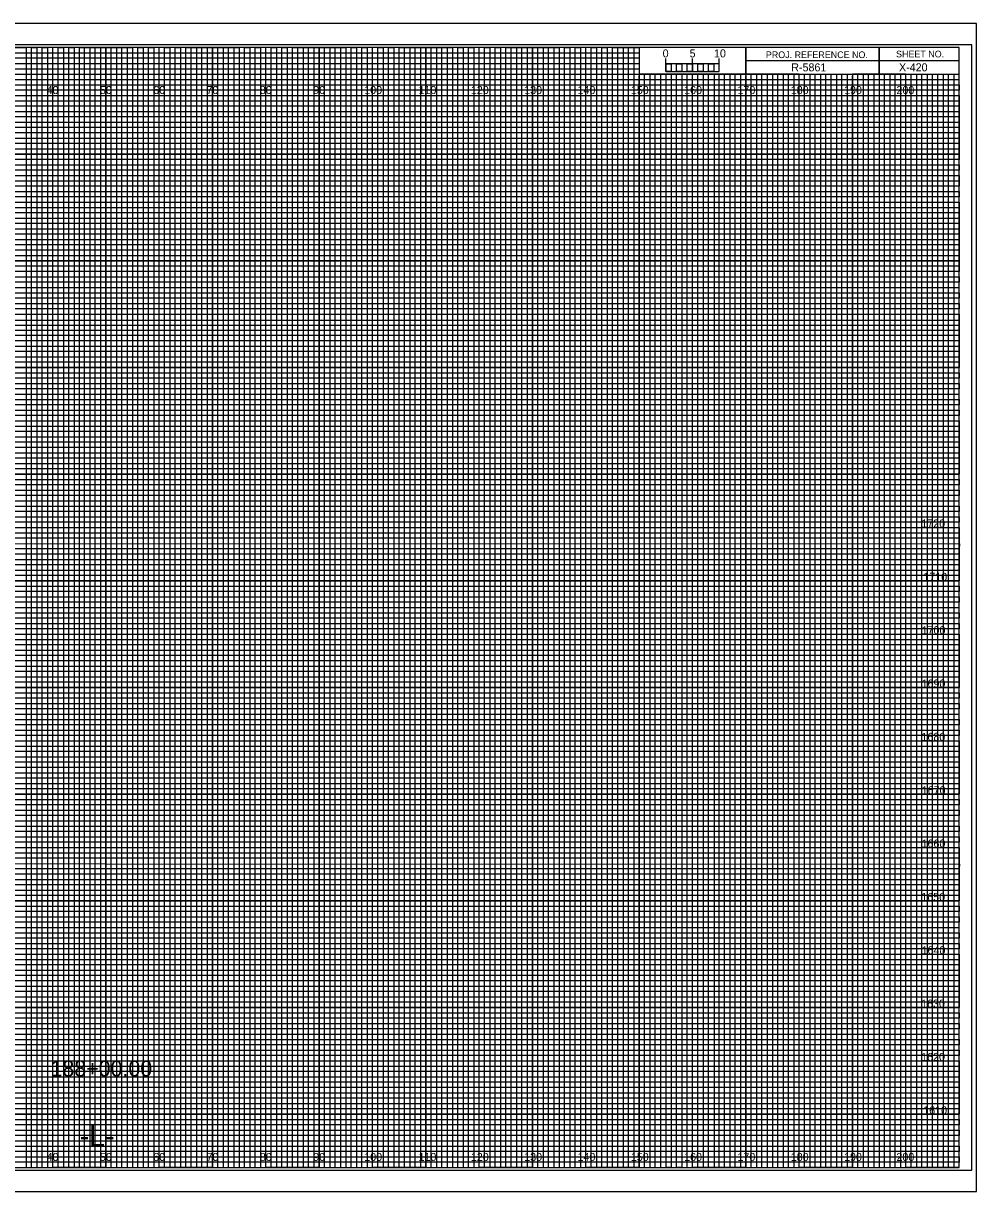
# Model space of a CAD drawing. Extents: x -13 to 323, y -5 to 6154.
# Drawn here: x 144.5 to 323.3, y 3515.5 to 3734.5 of the extents above; entities that cross this region are included whole.
import ezdxf

# ---------------------------------------------------------------- set-up
doc = ezdxf.new("R2010")
doc.units = 0
for name, color, linetype in [('Exist CMT Ground Line', 7, 'Continuous'), ('Prop Horizontal Alignment', 7, 'Continuous'), ('Prop Retaining Wall', 7, 'Continuous'), ('Prop XS Alignment Label', 7, 'Continuous'), ('Prop XS Bar Scale Labels', 7, 'Continuous'), ('Prop XS DDE', 7, 'Continuous'), ('Prop XS DDE Elevations', 7, 'Continuous'), ('Prop XS DDE Slope Text', 7, 'Continuous'), ('Prop XS Earthwork Shape', 7, 'Continuous'), ('Prop XS Elevation Labels', 7, 'Continuous'), ('Prop XS Project Number', 7, 'Continuous'), ('Prop XS Sheet Number', 7, 'Continuous'), ('Prop XS Station Labels', 7, 'Continuous'), ('Raster_Level_0', 7, 'Continuous'), ('Scratch_Level_3', 7, 'Continuous'), ('Sheet Cutting Line CELL', 7, 'Continuous')]:
    doc.layers.add(name, color=color, linetype=linetype)

msp = doc.modelspace()

# ---------------------------------------------------------------- linework, layer by layer
at = {"layer": 'Exist CMT Ground Line'}
for p, q in [((265, 3725.49), (265, 3727.9)), ((265, 3726.9), (265, 3727.9)), ((270, 3725.49), (270, 3727.9)), ((275, 3725.49), (275, 3727.9)), ((275, 3726.9), (275, 3727.9))]:
    msp.add_line(p, q, dxfattribs=at)
for points in [[(275, 3726.9), (265, 3726.9), (265, 3725.49), (275, 3725.49)], [(265, 3726.9), (266, 3726.9), (266, 3725.49), (265, 3725.49)], [(267, 3726.9), (268, 3726.9), (268, 3725.49), (267, 3725.49)], [(269, 3726.9), (270, 3726.9), (270, 3725.49), (269, 3725.49)], [(271, 3726.9), (272, 3726.9), (272, 3725.49), (271, 3725.49)], [(273, 3726.9), (274, 3726.9), (274, 3725.49), (273, 3725.49)]]:
    msp.add_lwpolyline(points, close=True, dxfattribs=at)
at = {"layer": 'Prop Retaining Wall'}
for p, q in [((0, 3729), (260, 3729)), ((260, 3727.98), (0, 3727.98)), ((260, 3729), (260, 3727.98)), ((0, 3727), (260, 3727)), ((260, 3725.89), (0, 3725.89)), ((260, 3727), (260, 3725.89)), ((0, 3724), (320, 3724))]:
    msp.add_line(p, q, dxfattribs=at)
for points in [[(0, 3723), (270, 3723), (320, 3723), (320, 3722), (0, 3722)], [(0, 3721), (320, 3721), (320, 3719), (0, 3719)], [(0, 3718), (320, 3718), (320, 3717), (0, 3716.98)], [(0, 3716), (320, 3716), (320, 3714), (0, 3714)], [(0, 3713), (320, 3713), (320, 3712), (0, 3712)], [(0, 3711), (320, 3711), (320, 3709), (0, 3709)], [(0, 3708), (320, 3708), (320, 3707), (0, 3707)], [(0, 3706), (320, 3706), (320, 3704), (0, 3704)], [(0, 3703), (320, 3703), (320, 3702), (0, 3702)], [(0, 3701), (320, 3701), (320, 3699), (0, 3699)], [(0, 3698), (320, 3698), (320, 3697), (0, 3697)], [(0, 3696), (320, 3696), (320, 3693.95), (320, 3693), (320, 3692), (0, 3692)], [(0, 3694), (320, 3694), (320, 3693), (0, 3693)], [(0, 3691), (320, 3691), (320, 3689), (0, 3689.03)], [(0, 3689.03), (320, 3689), (320, 3688), (0, 3688)], [(0, 3687), (320, 3687), (320, 3686), (0, 3686)], [(0, 3684), (320, 3684), (320, 3683), (0, 3683)], [(0, 3682), (320, 3682), (320, 3681), (0, 3681)], [(-0.07, 3678.89), (320, 3678.89), (320, 3677.88), (-0.07, 3677.88)], [(0, 3677), (320, 3677), (320, 3676), (0, 3676)], [(0, 3674), (320, 3674), (320, 3673), (0, 3673)], [(0, 3672), (320, 3672), (320, 3671), (0, 3671)], [(0, 3669), (320, 3669), (320, 3668), (0, 3668)], [(0, 3667), (320, 3667), (320, 3666), (0, 3666)], [(0, 3664), (320, 3664), (320, 3663), (0, 3663)], [(0, 3662), (320, 3662), (320, 3661), (0, 3661)], [(0, 3659), (320, 3659), (319.99, 3657.98), (0, 3658)], [(0, 3657), (320, 3657), (320, 3656), (0, 3656)], [(0, 3654), (320, 3654), (320, 3653), (0, 3653)], [(0, 3652), (320, 3652), (320, 3651), (0, 3651)], [(0, 3649), (320, 3649), (320, 3648), (0, 3648)], [(0, 3647), (320, 3647), (320, 3646), (0, 3646)], [(0, 3644), (320, 3644), (320, 3643), (0, 3643)], [(0, 3642), (320, 3642), (320, 3641), (0, 3641)], [(0, 3639), (320, 3639), (320, 3638), (0, 3638)], [(0, 3636.99), (320.07, 3636.91), (320, 3636), (0, 3636)], [(0, 3634), (320, 3634), (320, 3633), (0, 3633)], [(0, 3632), (320, 3632), (320, 3631), (0, 3631)], [(0, 3629), (320, 3629), (320, 3628), (0, 3628)], [(0, 3627), (320, 3627), (320, 3626), (0, 3626)], [(0, 3624), (320, 3624), (320, 3623), (0, 3623)], [(0, 3622), (320, 3622), (320, 3621), (0, 3621)], [(0, 3619), (320, 3619), (320, 3618), (0, 3618)], [(0, 3617), (320, 3617), (320, 3616), (0, 3616)], [(0, 3614), (320, 3614), (320, 3613), (0, 3613)], [(0, 3612), (320, 3612), (320, 3611), (0, 3611)], [(0, 3609), (320, 3609), (320, 3608), (0, 3608)], [(0, 3607), (320, 3607), (320, 3606), (0, 3606)], [(0, 3604), (320, 3604), (320, 3603), (0, 3603)], [(0, 3602), (320, 3602), (320, 3601), (0, 3601)], [(0, 3599), (320, 3599), (319.99, 3597.98), (0, 3598)], [(0, 3597), (320, 3597), (320, 3596), (0, 3596)], [(0, 3594), (320, 3594), (320, 3593), (0, 3593)], [(0, 3592), (320, 3592), (320, 3591), (0, 3591)], [(0, 3589), (320, 3589), (320, 3588), (0, 3588)], [(0, 3587), (320, 3587), (320, 3586), (0, 3586)], [(0, 3584), (320, 3584), (320, 3583), (0, 3583)], [(0, 3582), (320, 3582), (320, 3581), (0, 3581)], [(0, 3579), (320, 3579), (320, 3578), (0, 3578)], [(0, 3576.99), (320.07, 3576.91), (320, 3576), (0, 3576)], [(0, 3574), (320, 3574), (320, 3573), (0, 3573)], [(0, 3572), (320, 3572), (320, 3571), (0, 3571)], [(0, 3569), (320, 3569), (320, 3568), (0, 3568)], [(0, 3567), (320, 3567), (320, 3566), (0, 3566)], [(0, 3564), (320, 3564), (320, 3563), (0, 3563)], [(0, 3562), (320, 3562), (320, 3561), (0, 3561)], [(0, 3559), (320, 3559), (320, 3558), (0, 3558)], [(0, 3557), (320, 3557), (320, 3556), (0, 3556)], [(0, 3554), (320, 3554), (320, 3553), (0, 3553)], [(0, 3552), (320, 3552), (320, 3551), (0, 3551)], [(0, 3549), (320, 3549), (320, 3548), (0, 3548)], [(0, 3547), (320, 3547), (320, 3546), (0, 3546)], [(0, 3544), (320, 3544), (320, 3543), (0, 3543)], [(0, 3542), (320, 3542), (320, 3541), (0, 3541)], [(0, 3539), (320, 3539), (320, 3538), (0, 3538)], [(0, 3537), (320, 3537), (320, 3536), (0, 3536)], [(0, 3534), (320, 3534), (320, 3533), (0, 3533)], [(0, 3532), (320, 3532), (320, 3531), (0, 3531)], [(0, 3529), (320, 3529), (320, 3528), (0, 3528)], [(0, 3527), (320, 3527), (320, 3526), (0, 3526)], [(0, 3524), (320, 3524), (320, 3523), (0, 3523)], [(0, 3522), (320, 3522), (320, 3521), (0, 3521)]]:
    msp.add_lwpolyline(points, dxfattribs=at)
at = {"layer": 'Prop XS Alignment Label'}
for p, q in [((305, 3730), (305, 3725)), ((305, 3725), (305, 3730)), ((280, 3727.5), (280, 3725)), ((320, 3727.49), (280, 3727.49)), ((280, 3725), (320, 3725))]:
    msp.add_line(p, q, dxfattribs=at)
for points in [[(320, 3730), (0, 3730), (0, 3520), (320, 3520)], [(280, 3730), (260, 3730), (260, 3725.03), (280, 3725.03)], [(320, 3730), (280, 3730), (280, 3725), (320, 3725)]]:
    msp.add_lwpolyline(points, close=True, dxfattribs=at)
at = {"layer": 'Prop XS DDE'}
msp.add_lwpolyline([(-13.4, 3515.5), (323.3, 3515.5), (323.3, 3734.5), (-13.4, 3734.5)], close=True, dxfattribs=at)
at = {"layer": 'Prop XS DDE Elevations'}
for p, q in [((150, 3520), (150, 3730)), ((160, 3520), (160, 3730)), ((170, 3520), (170, 3730)), ((180, 3520), (180, 3730)), ((190, 3520), (190, 3730)), ((200, 3520), (200, 3730)), ((210, 3520), (210, 3730)), ((220, 3520), (220, 3730)), ((230, 3520), (230, 3730)), ((240, 3520), (240, 3730)), ((250, 3520), (250, 3730)), ((260, 3520), (260, 3724.69)), ((270, 3520), (270, 3724.69)), ((280, 3520), (280, 3724.69)), ((290, 3520), (290, 3724.69)), ((300, 3520), (300, 3724.69)), ((310, 3520), (310, 3724.69)), ((0, 3720), (320, 3720)), ((0, 3710), (320, 3710)), ((0, 3700), (320, 3700)), ((0, 3690), (320, 3690)), ((0, 3680), (320, 3680)), ((0, 3670), (320, 3670)), ((0, 3660), (320, 3660)), ((0, 3650), (320, 3650)), ((0, 3640), (320, 3640)), ((0, 3630), (320, 3630)), ((0, 3620), (320, 3620)), ((0, 3610), (320, 3610)), ((0, 3600), (320, 3600)), ((0, 3590), (320, 3590)), ((0, 3580), (320, 3580)), ((0, 3570), (320, 3570)), ((0, 3560), (320, 3560)), ((0, 3550), (320, 3550)), ((0, 3540), (320, 3540)), ((0, 3530), (320, 3530))]:
    msp.add_line(p, q, dxfattribs=at)
at = {"layer": 'Prop XS DDE Slope Text'}
msp.add_lwpolyline([(-10.8, 3519.5), (322.4, 3519.5), (322.4, 3730.5), (-10.8, 3730.5)], close=True, dxfattribs=at)
at = {"layer": 'Prop XS Earthwork Shape'}
for p, q in [((150, 3730), (140, 3730)), ((150, 3520), (150, 3730)), ((170, 3730), (160, 3730)), ((160, 3730), (160, 3520)), ((170, 3520), (170, 3730)), ((190, 3730), (180, 3730)), ((180, 3730), (180, 3520)), ((190, 3520), (190, 3730)), ((210, 3730), (200, 3730)), ((200, 3730), (200, 3520)), ((210, 3520), (210, 3730)), ((230, 3730), (220, 3730)), ((220, 3730), (220, 3520)), ((230, 3520), (230, 3730)), ((250, 3730), (240, 3730)), ((240, 3730), (240, 3520)), ((250, 3520), (250, 3730)), ((260, 3730), (260, 3520)), ((270, 3520), (270, 3725)), ((290, 3725), (280, 3725)), ((280, 3725), (280, 3520)), ((290, 3520), (290, 3725)), ((310, 3725), (300, 3725)), ((300, 3725), (300, 3520)), ((310, 3520), (310, 3725)), ((160, 3520), (150, 3520)), ((180, 3520), (170, 3520)), ((200, 3520), (190, 3520)), ((220, 3520), (210, 3520)), ((240, 3520), (230, 3520)), ((260, 3520), (250, 3520)), ((280, 3520), (270, 3520)), ((300, 3520), (290, 3520)), ((320, 3520), (310, 3520)), ((320, 3520), (320, 3520))]:
    msp.add_line(p, q, dxfattribs=at)
for points in [[(0, 3720), (320, 3720), (320, 3710), (0, 3710)], [(0, 3700), (320, 3700), (320, 3690), (0, 3690)], [(0, 3680), (320, 3680), (320, 3670), (0, 3670)], [(0, 3660), (320, 3660), (320, 3650), (0, 3650)], [(0, 3640), (320, 3640), (320, 3630), (0, 3630)], [(0, 3620), (320, 3620), (320, 3610), (0, 3610)], [(0, 3600), (320, 3600), (320, 3590), (0, 3590)], [(0, 3580), (320, 3580), (320, 3570), (0, 3570)], [(0, 3560), (320, 3560), (320, 3550), (0, 3550)], [(0, 3540), (320, 3540), (320, 3530), (0, 3530)]]:
    msp.add_lwpolyline(points, dxfattribs=at)
at = {"layer": 'Prop XS Elevation Labels'}
for p, q in [((267, 3725), (266.01, 3725)), ((266.01, 3725), (266.01, 3520)), ((267, 3520), (267, 3725)), ((269, 3725), (268, 3725)), ((268, 3725), (268, 3520)), ((269, 3520), (269, 3725)), ((266.01, 3520), (265, 3520)), ((268, 3520), (267, 3520))]:
    msp.add_line(p, q, dxfattribs=at)
for points in [[(145, 3520), (146, 3520), (146, 3730), (147, 3730), (147, 3520)], [(147, 3520), (148, 3520), (148, 3730), (149, 3730), (149, 3520)], [(150, 3520), (151, 3520), (151, 3730), (152, 3730), (152, 3520)], [(152, 3520), (153, 3520), (153, 3730), (154, 3730), (154, 3520)], [(155, 3520), (156, 3520), (156, 3730), (157, 3730), (157, 3520)], [(157, 3520), (158, 3520), (158, 3730), (159, 3730), (159, 3520)], [(160, 3520), (161, 3520), (161, 3730), (162, 3730), (162, 3520)], [(162, 3520), (163, 3520), (163, 3730), (164, 3730), (164, 3520)], [(165, 3520), (166, 3520), (166, 3730), (167, 3730), (167, 3520)], [(167, 3520), (168, 3520), (168, 3730), (169, 3730), (169, 3520)], [(170, 3520), (171, 3520), (171, 3730), (172, 3730), (172, 3520)], [(172, 3520), (173, 3520), (173, 3730), (174, 3730), (174, 3520)], [(175, 3520), (176, 3520), (176, 3730), (177, 3730), (177, 3520)], [(177, 3520), (178, 3520), (178, 3730), (179, 3730), (179, 3520)], [(180, 3520), (181, 3520), (181, 3730), (182, 3730), (182, 3520)], [(182, 3520), (183, 3520), (183, 3730), (184, 3730), (184, 3520)], [(185, 3520), (186, 3520), (186, 3730), (187, 3730), (187, 3520)], [(187, 3520), (188, 3520), (188, 3730), (189, 3730), (189, 3520)], [(190, 3520), (191, 3520), (191, 3730), (192, 3730), (192, 3520)], [(192, 3520), (193, 3520), (193, 3730), (194, 3730), (194, 3520)], [(195, 3520), (196, 3520), (196, 3730), (197, 3730), (197, 3520)], [(197, 3520), (198, 3520), (198, 3730), (199, 3730), (199, 3520)], [(200, 3520), (201, 3520), (201, 3730), (202, 3730), (202, 3520)], [(202, 3520), (203, 3520), (203, 3730), (204, 3730), (204, 3520)], [(205, 3520), (206, 3520), (206, 3730), (207, 3730), (207, 3520)], [(207, 3520), (208, 3520), (208, 3730), (209, 3730), (209, 3520)], [(210, 3520), (211, 3520), (211, 3730), (212, 3730), (212, 3520)], [(212, 3520), (213, 3520), (213, 3730), (214, 3730), (214, 3520)], [(215, 3520), (216, 3520), (216, 3730), (217, 3730), (217, 3520)], [(217, 3520), (218, 3520), (218, 3730), (219, 3730), (219, 3520)], [(220, 3520), (221, 3520), (221, 3730), (222, 3730), (222, 3520)], [(222, 3520), (223, 3520), (223, 3730), (224, 3730), (224, 3520)], [(225, 3520), (226, 3520), (226, 3730), (227, 3730), (227, 3520)], [(227, 3520), (228, 3520), (228, 3730), (229, 3730), (229, 3520)], [(230, 3520), (231, 3520), (231, 3730), (232, 3730), (232, 3520)], [(232, 3520), (233, 3520), (233, 3730), (234, 3730), (234, 3520)], [(235, 3520), (236, 3520), (236, 3730), (237, 3730), (237, 3520)], [(237, 3520), (238, 3520), (238, 3730), (239, 3730), (239, 3520)], [(240, 3520), (241, 3520), (241, 3730), (242, 3730), (242, 3520)], [(242, 3520), (243, 3520), (243, 3730), (244, 3730), (244, 3520)], [(245, 3520), (246, 3520), (246, 3730), (247, 3730), (247, 3520)], [(247, 3520), (248, 3520), (248, 3730), (249, 3730), (249, 3520)], [(250, 3520), (251, 3520), (251, 3730), (252, 3730), (252, 3520)], [(252, 3520), (253, 3520), (253, 3730), (254, 3730), (254, 3520)], [(255, 3520), (256, 3520), (256, 3730), (257, 3730), (257, 3520)], [(257, 3520), (258, 3520), (258, 3730), (259, 3730), (259, 3520)], [(260, 3520), (261, 3520), (261, 3725), (262.02, 3725), (262.02, 3520)], [(262, 3520), (263, 3520), (263, 3725), (263.99, 3725), (263.99, 3520)], [(270, 3520), (270.98, 3520), (270.98, 3725), (272, 3725), (272, 3520)], [(272, 3520), (273, 3520), (273, 3725), (274.05, 3725), (274.05, 3520)], [(275, 3520), (276, 3520), (276, 3725), (277, 3725), (277, 3520)], [(277, 3520), (278, 3520), (278, 3725), (279, 3725), (279, 3520)], [(280, 3520), (281, 3520), (281, 3725), (282, 3725), (282, 3520)], [(282, 3520), (283, 3520), (283, 3725), (284, 3725), (284, 3520)], [(285, 3520), (286, 3520), (286, 3725), (287, 3725), (287, 3520)], [(287, 3520), (288, 3520), (288, 3725), (289, 3725), (289, 3520)], [(290, 3520), (291, 3520), (291, 3725), (292, 3725), (292, 3520)], [(292, 3520), (293, 3520), (293, 3725), (294, 3725), (294, 3520)], [(295, 3520), (296, 3520), (296, 3725), (297, 3725), (297, 3520)], [(297, 3520), (298, 3520), (298, 3725), (299, 3725), (299, 3520)], [(300, 3520), (301, 3520), (301, 3725), (302, 3725), (302, 3520)], [(302, 3520), (303, 3520), (303, 3725), (304, 3725), (304, 3520)], [(305, 3520), (306, 3520), (306, 3725), (307, 3725), (307, 3520)], [(307, 3520), (308, 3520), (308, 3725), (309, 3725), (309, 3520)], [(310, 3520), (311, 3520), (311, 3725), (312, 3725), (312, 3520)], [(312, 3520), (313, 3520), (313, 3725), (314, 3725), (314, 3520)], [(315, 3520), (316, 3520), (316, 3725), (317, 3725), (317, 3520)], [(317, 3520), (318, 3520), (318, 3725), (319, 3725), (319, 3520)]]:
    msp.add_lwpolyline(points, dxfattribs=at)
at = {"layer": 'Prop XS Station Labels'}
for points in [[(135, 3730), (145, 3730), (145, 3520), (155, 3520), (155, 3730), (165, 3730), (165, 3520), (175, 3520), (175, 3730), (185, 3730), (185, 3520), (195, 3520), (195, 3730), (205, 3730), (205, 3520), (215, 3520), (215, 3730), (225, 3730), (225, 3520), (235, 3520), (235, 3730), (245, 3730), (245, 3520), (255, 3520), (255, 3730), (259.93, 3730), (260, 3730), (260, 3725), (264.99, 3725), (264.99, 3520), (275, 3520), (275, 3725), (285, 3725), (285, 3520), (295, 3520), (295, 3725), (305, 3725), (305, 3520), (315, 3520), (315, 3725)], [(0, 3725), (275, 3725)], [(0, 3705), (320, 3705), (320, 3715), (0, 3715)], [(0, 3685), (320, 3685), (320, 3695), (0, 3695)], [(0, 3665), (320, 3665), (320, 3675), (0, 3675)], [(0, 3645), (320, 3645), (320, 3655), (0, 3655)], [(0, 3625), (320, 3625), (320, 3635), (0, 3635)], [(0, 3605), (320, 3605), (320, 3615), (0, 3615)], [(0, 3585), (320, 3585), (320, 3595), (0, 3595)], [(0, 3565), (320, 3565), (320, 3575), (0, 3575)], [(0, 3545), (320, 3545), (320, 3555), (0, 3555)], [(0, 3525), (320, 3525), (320, 3535), (0, 3535)]]:
    msp.add_lwpolyline(points, dxfattribs=at)
at = {"layer": 'Sheet Cutting Line CELL'}
for p, q in [((323.3, 3734.5), (-13.4, 3734.5)), ((-13.4, 3515.5), (323.3, 3515.5))]:
    msp.add_line(p, q, dxfattribs=at)

# ---------------------------------------------------------------- texts
at = {"layer": 'Exist CMT Ground Line'}
msp.add_text('0', height=1.5, dxfattribs=at).set_placement((264.41, 3728.12))
at = {"layer": 'Prop Horizontal Alignment'}
msp.add_text('188+00.00', height=3, dxfattribs=at).set_placement((149.59, 3537.09))
at = {"layer": 'Prop XS Alignment Label'}
for s, height, p in [('PROJ. REFERENCE NO.', 1.25, (283.77, 3727.99)), ('SHEET NO.', 1.25, (308.19, 3728.12)), ('-L-', 4, (155.06, 3524))]:
    msp.add_text(s, height=height, dxfattribs=at).set_placement(p)
at = {"layer": 'Prop XS Bar Scale Labels'}
for s, p in [('5', (269.47, 3728.12)), ('10', (274.04, 3728.12))]:
    msp.add_text(s, height=1.5, dxfattribs=at).set_placement(p)
at = {"layer": 'Prop XS Project Number'}
msp.add_text('R-5861', height=1.5, dxfattribs=at).set_placement((288.53, 3725.5))
at = {"layer": 'Prop XS Sheet Number'}
msp.add_text('X-420', height=1.5, dxfattribs=at).set_placement((308.74, 3725.51))
at = {"layer": 'Raster_Level_0'}
for s, p in [('40', (148.86, 3721.25)), ('50', (158.86, 3721.25)), ('60', (168.86, 3721.25)), ('70', (178.86, 3721.25)), ('80', (188.86, 3721.25)), ('90', (198.86, 3721.25)), ('100', (208.44, 3721.25)), ('110', (218.62, 3721.25)), ('120', (228.44, 3721.25)), ('130', (238.44, 3721.25)), ('140', (248.44, 3721.25)), ('150', (258.44, 3721.25)), ('160', (268.44, 3721.25)), ('170', (278.44, 3721.25)), ('180', (288.44, 3721.25)), ('190', (298.44, 3721.25)), ('200', (308.26, 3721.25)), ('40', (148.86, 3521.25)), ('50', (158.86, 3521.25)), ('60', (168.86, 3521.25)), ('70', (178.86, 3521.25)), ('80', (188.86, 3521.25)), ('90', (198.86, 3521.25)), ('100', (208.44, 3521.25)), ('110', (218.62, 3521.25)), ('120', (228.44, 3521.25)), ('130', (238.44, 3521.25)), ('140', (248.44, 3521.25)), ('150', (258.44, 3521.25)), ('160', (268.44, 3521.25)), ('170', (278.44, 3521.25)), ('180', (288.44, 3521.25)), ('190', (298.44, 3521.25)), ('200', (308.26, 3521.25))]:
    msp.add_text(s, height=1.5, dxfattribs=at).set_placement(p)
at = {"layer": 'Scratch_Level_3'}
for s, p in [('1720', (312.93, 3640)), ('1710', (313.31, 3630)), ('1700', (312.98, 3620)), ('1690', (312.97, 3610)), ('1680', (312.95, 3600)), ('1670', (313, 3590)), ('1660', (312.97, 3580)), ('1650', (312.92, 3570)), ('1640', (312.97, 3560)), ('1630', (312.89, 3550)), ('1620', (312.9, 3540)), ('1610', (313.28, 3530))]:
    msp.add_text(s, height=1.5, dxfattribs=at).set_placement(p)

doc.saveas('drawing.dxf')
